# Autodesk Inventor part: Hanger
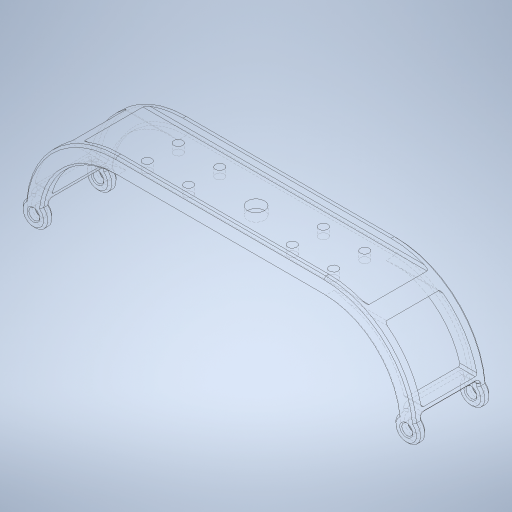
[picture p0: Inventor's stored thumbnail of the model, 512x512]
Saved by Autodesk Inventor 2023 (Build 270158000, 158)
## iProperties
Created: 2023-11
Part Number: Hanger
Material: Generic
Document SubType Name: Modeling
Designer: tornqvih
Density: 1 g/cm^3
Appearance: Default
Mass: 255.059 g
Surface Area: 645.137 cm^2
Volume: 255.059 cm^3
Author: tornqvih
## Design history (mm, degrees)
sketch "Sketch1"
  geometry: L1 (-100.502, 8)-(100.502, 8); L2 (-100.502, -8)-(100.502, -8); L3 (-284.58, 0)-(284.58, 0) reference; L4 (0, -115.369)-(0, 48.216) reference; A1 r 12 centre (-180, -80) between (-188.05, -71.101) and (-171.95, -71.101); A2 r 12 centre (180, -80) between (171.95, -71.101) and (188.05, -71.101); A3 r 88 centre (-100.502, -80) between (-100.502, 8) and (-188.05, -71.101); A4 r 72 centre (-100.502, -80) between (-100.502, -8) and (-171.95, -71.101); A5 r 88 centre (100.502, -80) between (188.05, -71.101) and (100.502, 8); A6 r 72 centre (100.502, -80) between (171.95, -71.101) and (100.502, -8); 1 further point
  constraints: 12 point on circle, 7 symmetric about line, 6 centre point, 4 end point, 2 coincident, 2 horizontal alignment, 1 horizontal, 1 vertical alignment
  dimensions: "d0" = 8 distance between parallel lines of L3 L1; "d1" = 180 distance from line of L4 A1.centre; "d2" = 12 radius of A1; "d5" = 80 distance from line of L3 A1.centre
extrude "Extrusion1" new body sketch "Sketch1" distance "d7" = 70; taper "d8" = 0 deg
sketch "Sketch2"
  geometry: L1 (0, -112)-(0, 28) reference; L2 (-268.8, 0)-(268.8, 0) reference; 3 further points
  constraints: 1 symmetric about line
  dimensions: "d9" = 180 distance from line of L1 point (-180, -80); "d10" = 80 distance from line of L2 point (-180, -80)
hole "Hole1" sketch "Sketch2" at (-180, -80), (180, -80) diameter "d11" = 10.5; stored, may be unused: countersink angle "d15" = 90 deg, drill point angle "d17" = 118 deg; dims "d12" = 6, "d13" = 4, "d14" = 2, "d16" = 8
sketch "Sketch4"
  geometry: L1 (0, -9.5)-(0, 57) reference; L2 (-100.502, 0)-(100.502, 0) reference; 9 further points
  constraints: 4 symmetric about line, 2 horizontal alignment, 2 vertical alignment
  dimensions: "d23" = 40 distance of point (50, 20) point (90, 20); "d24" = 30 distance of point (90, 50) point (90, 20); "d25" = 20 distance from line of L2 point (90, 20); "d26" = 180 distance of point (-90, 20) point (90, 20)
hole "Hole2" sketch "Sketch4" at (90, 20), (50, 20), (90, 50), (50, 50), (-50, 20), (-90, 20), (-50, 50), (-90, 50) diameter "d27" = 8.5; stored, may be unused: countersink angle "d31" = 90 deg, drill point angle "d33" = 118 deg; dims "d28" = 6, "d29" = 4, "d30" = 2, "d32" = 8
sketch "Sketch5"
  geometry: L1 (-8, 62)-(-62.101, 62); L2 (-62.101, 62)-(-62.101, 8); L3 (-62.101, 8)-(-8, 8); L4 (-8, 8)-(-8, 62); L5 (-8, 0)-(-8, 70) reference; L6 (-154.121, 0)-(35.02, 0) reference; L7 (-67.101, 62)-(-127.101, 62); L8 (-127.101, 62)-(-127.101, 8); L9 (-127.101, 8)-(-67.101, 8); L10 (-67.101, 8)-(-67.101, 62); L11 (8, 70)-(-71.101, 70) reference; L12 (8, 0)-(8, 70) reference; L13 (-71.101, 0)-(-71.101, 70) reference; L14 (-71.101, 70)-(-92, 70) reference; L15 (8, 65)-(0, 65); L16 (0, 65)-(0, 5); L17 (0, 5)-(8, 5); L18 (8, 5)-(8, 65); 2 further points
  constraints: 24 end point, 6 parallel, 3 horizontal, 3 perpendicular, 2 horizontal alignment, 2 point on line
  dimensions: "d37" = 8 distance between parallel lines of L6 L3; "d41" = 60 distance of L8.end L9.end; "d63" = 4 distance between parallel lines of L13 L10; "d64" = 5 distance between parallel lines of L10 L2; "d72" = 8 distance between parallel lines of L14 L7; "d88" = 8 distance between parallel lines of L4 L16; "d89" = 5 distance between parallel lines of L11 L15; "d90" = 5 distance between parallel lines of L6 L17
extrude "Extrusion2" cut sketch "Sketch5" stored distance "d38" = 400; taper "d39" = 0 deg
sketch "Sketch7"
  geometry: L1 (0, -6.5)-(0, 39) reference; L2 (-100.502, 0)-(100.502, 0) reference; 2 further points
  constraints: 1 point on line
  dimensions: "d43" = 35 distance from line of L2 point (0, 35)
hole "Hole3" sketch "Sketch7" at (0, 35) diameter "d44" = 16.5; stored, may be unused: countersink angle "d48" = 90 deg, drill point angle "d50" = 118 deg; dims "d45" = 6, "d46" = 4, "d47" = 2, "d49" = 8
fillet "Fillet2" dims "d65" = 2
chamfer "Chamfer2" distance "d55" = 1; stored, may be unused: second distance "d56" = 2, angle "d57" = 45 deg
chamfer "Chamfer3" distance "d66" = 2; stored, may be unused: second distance "d67" = 2, angle "d68" = 45 deg
chamfer "Chamfer4" distance "d69" = 2; stored, may be unused: second distance "d70" = 2, angle "d71" = 45 deg
body "Solid1"
